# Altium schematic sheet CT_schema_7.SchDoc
size 368 x 245 mm
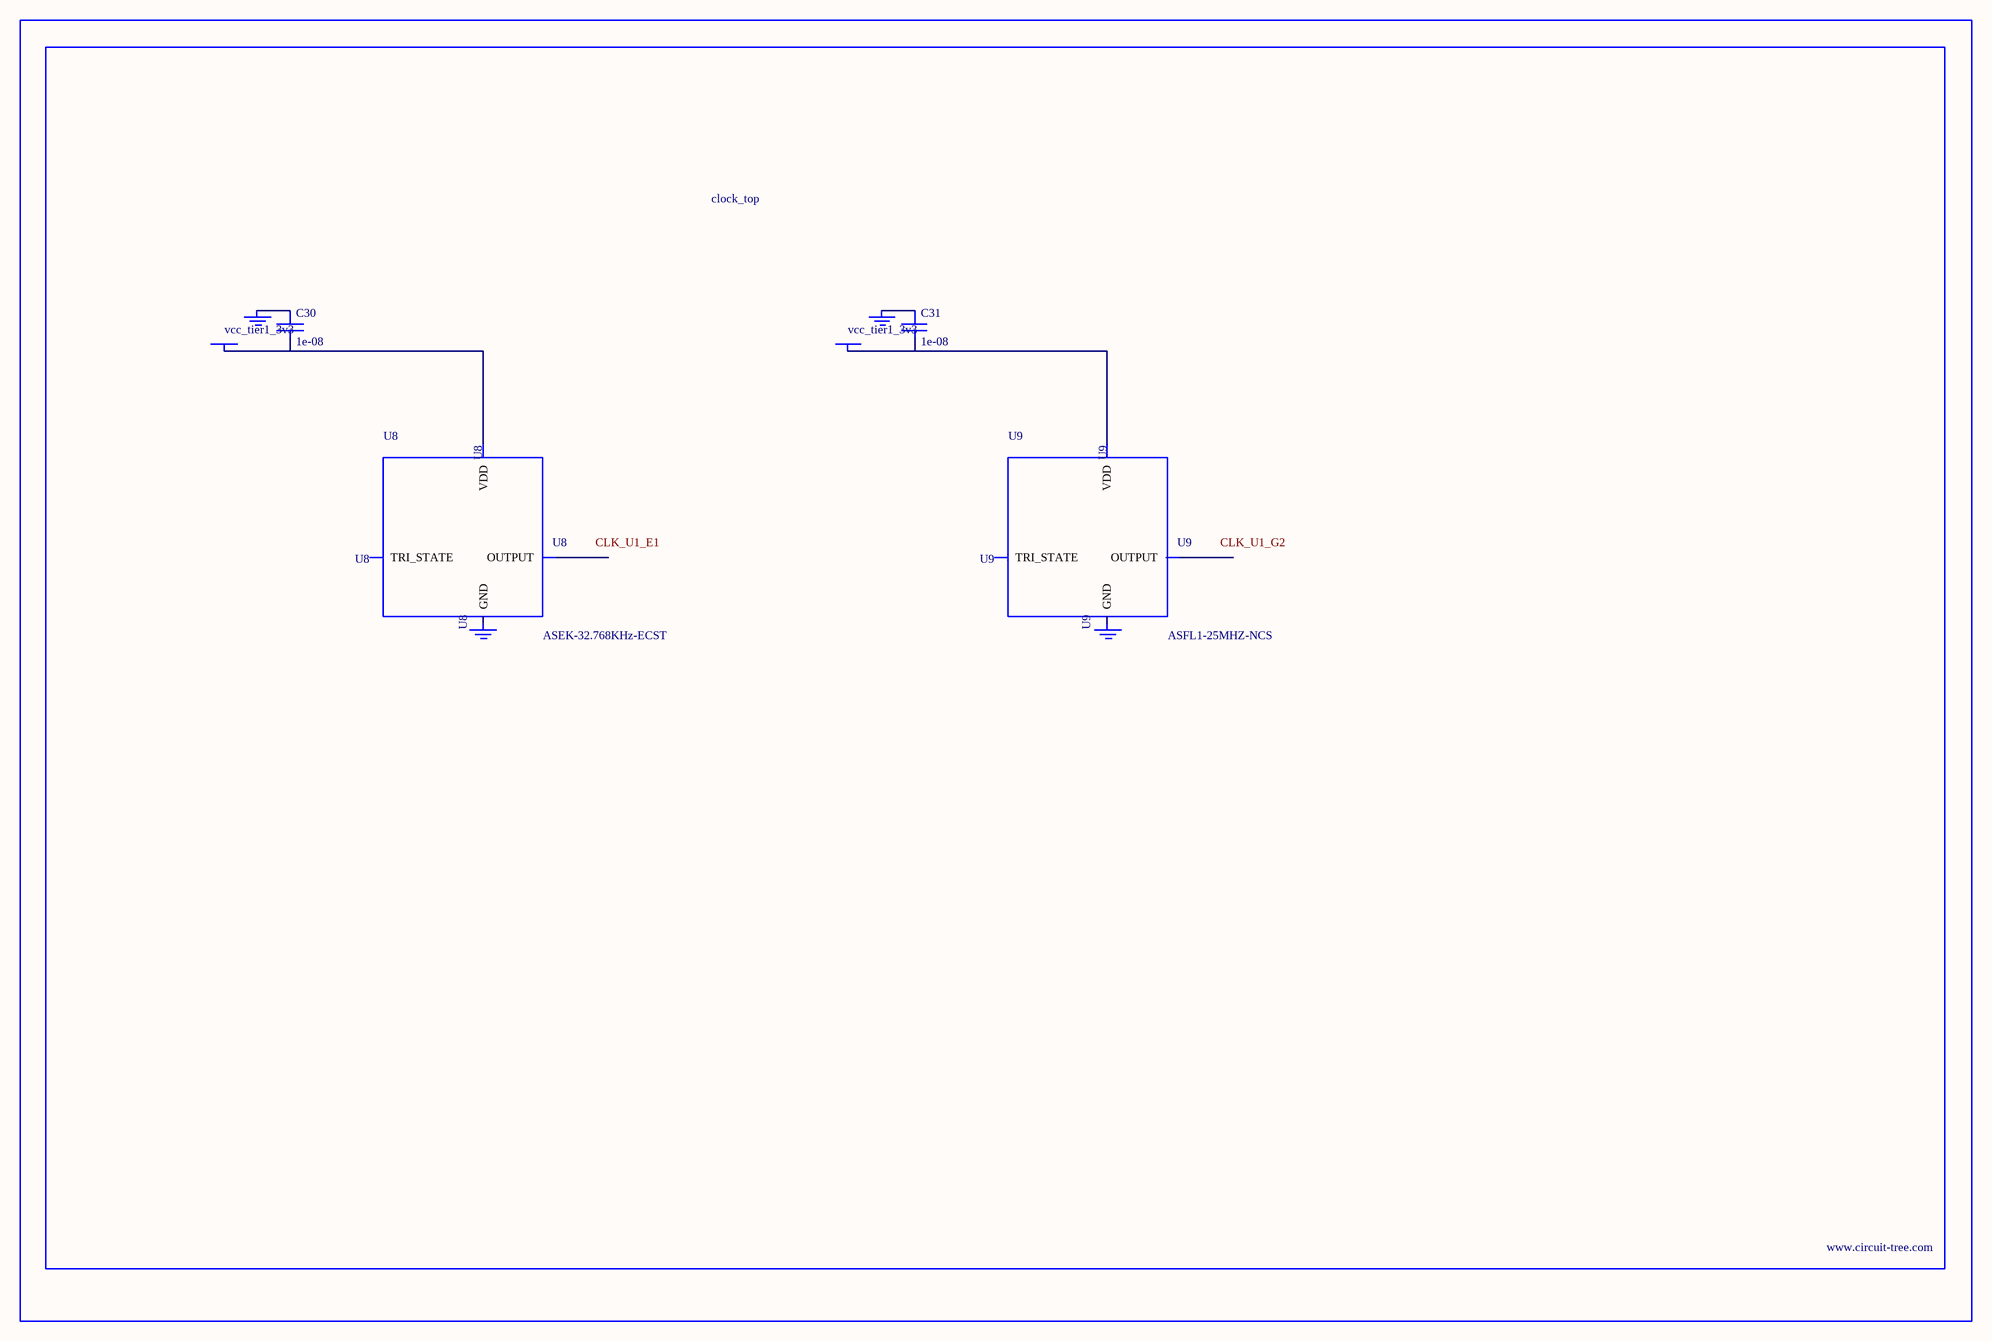
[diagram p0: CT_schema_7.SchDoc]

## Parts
BORDER6  (no value)
C30  1e-08  [C0402]
C31  1e-08  [C0402]
GND_INSTANCE_6_0  (no value)
GND_INSTANCE_6_1  (no value)
GND_INSTANCE_6_2  (no value)
GND_INSTANCE_6_3  (no value)
POWER_INSTANCE_6_0  vcc_tier1_3v3
POWER_INSTANCE_6_1  vcc_tier1_3v3
U8  ASEK-32.768KHz-ECST  [ASEK]
U9  ASFL1-25MHZ-NCS  [ASFL1]

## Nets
NetC30_1: C30.1 GND_INSTANCE_6_0.0(GND)
NetC30_2: C30.2 POWER_INSTANCE_6_0.0(PWR) U8.4(VDD)
NetC31_1: C31.1 GND_INSTANCE_6_2.0(GND)
NetC31_2: C31.2 POWER_INSTANCE_6_1.0(PWR) U9.4(VDD)

Not connected (* = marked no-connect by the designer): GND_INSTANCE_6_1 0(GND); GND_INSTANCE_6_3 0(GND); U8 1(TRI_STATE) 2(GND) 3(OUTPUT); U9 1(TRI_STATE) 2(GND) 3(OUTPUT)

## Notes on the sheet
- Labels drawn without touching a wire or pin: CLK_U1_E1, CLK_U1_G2

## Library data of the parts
BORDER6 = BORDER_PAGE6
C30 C31 = C0402C103K3RAC
GND_INSTANCE_6_0-GND_INSTANCE_6_3 = GND
POWER_INSTANCE_6_0 POWER_INSTANCE_6_1 = PWR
